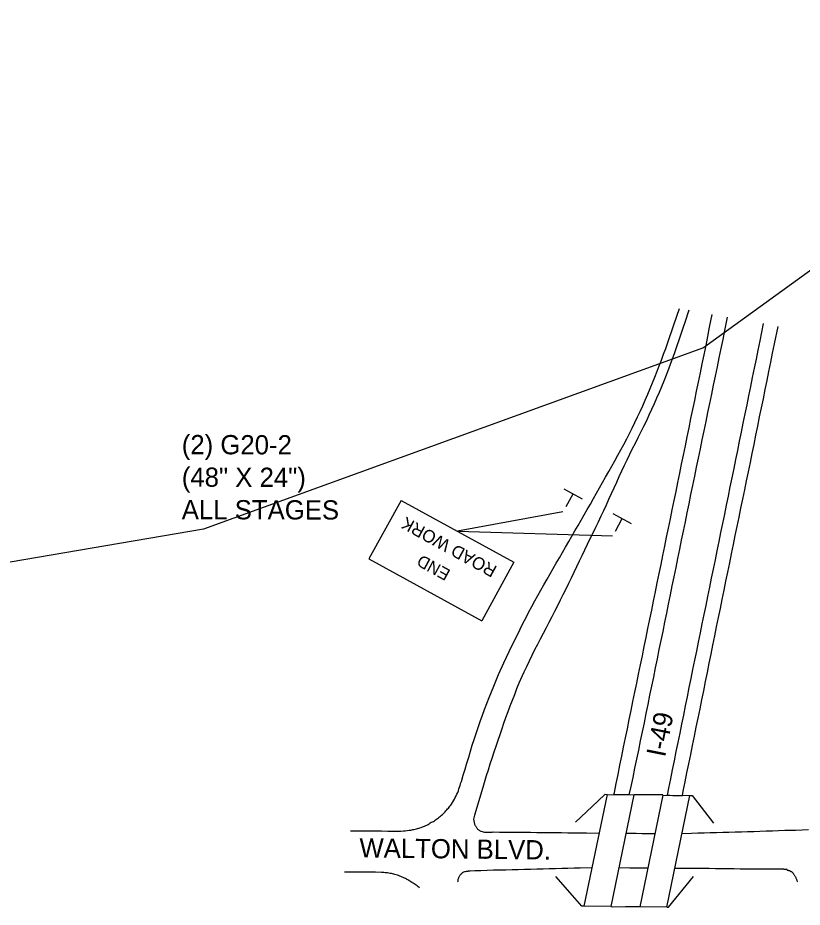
# Model space of a CAD drawing. Extents: x 1017892 to 1236694, y 658811 to 792468.
# Drawn here: x 1022369 to 1023001, y 659671 to 660387 of the extents above; entities that cross this region are included whole.
import ezdxf

# ---------------------------------------------------------------- set-up
doc = ezdxf.new("R2010")
doc.units = 0
for name, color, linetype in [('Level 3', 7, 'Continuous'), ('Level 42', 7, 'Continuous'), ('Level 8', 7, 'Continuous'), ('R_Border', 7, 'Continuous'), ('R_Proposed Road Annot', 7, 'Continuous'), ('S_BRIDGE', 7, 'Continuous'), ('S_EDGE_PAVEMENT', 7, 'Continuous'), ('S_MISC_STRUCTURES', 7, 'Continuous'), ('S_SIDEWALK', 7, 'Continuous')]:
    doc.layers.add(name, color=color, linetype=linetype)

msp = doc.modelspace()

# ---------------------------------------------------------------- linework, layer by layer
at = {"layer": 'Level 3'}
for p, q in [((1022809.12, 660007.57), (1022823.96, 659999.55)), ((1022816.38, 660003.36), (1022810.91, 659993.23)), ((1022848.64, 659987.77), (1022863.48, 659979.74)), ((1022855.91, 659983.56), (1022850.43, 659973.43))]:
    msp.add_line(p, q, dxfattribs=at)
at = {"layer": 'Level 8'}
for p, q in [((1022678.06, 659998.42), (1022652.2, 659951.32)), ((1022678.06, 659998.42), (1022768.89, 659948.54)), ((1022652.2, 659951.32), (1022743.02, 659901.44)), ((1022768.89, 659948.54), (1022743.02, 659901.44))]:
    msp.add_line(p, q, dxfattribs=at)
at = {"layer": 'R_Border'}
for points in [[(1023548.14, 660387), (1023255.62, 660362.67), (1022921.74, 660121.31)], [(1022921.74, 660121.31), (1022518.9, 659975.15), (1021256.99, 659760.06)]]:
    msp.add_lwpolyline(points, dxfattribs=at)
at = {"layer": 'R_Proposed Road Annot'}
for p, q in [((1022808.5, 659989.3), (1022723.48, 659973.48)), ((1022723.48, 659973.48), (1022848.36, 659969.93))]:
    msp.add_line(p, q, dxfattribs=at)
at = {"layer": 'S_BRIDGE'}
for points in [[(1022847.15, 659671.44), (1022825.68, 659671.68), (1022844.27, 659761.47), (1022865.63, 659761.4), (1022847.15, 659671.44)], [(1022870.74, 659671.19), (1022889.14, 659761.02), (1022910.5, 659760.84), (1022891.96, 659670.94), (1022870.74, 659671.19)]]:
    msp.add_lwpolyline(points, dxfattribs=at)
at = {"layer": 'S_EDGE_PAVEMENT'}
for points in [[(1022677.93, 659732.15), (1022679.95, 659732.26), (1022681.45, 659732.38), (1022682.95, 659732.56), (1022684.46, 659732.75), (1022685.95, 659732.94), (1022687.42, 659733.24), (1022688.43, 659733.46), (1022689.41, 659733.7), (1022690.39, 659733.94), (1022691.36, 659734.14), (1022692.33, 659734.34), (1022693.29, 659734.65), (1022694.26, 659735.04), (1022695.21, 659735.43), (1022696.18, 659735.72), (1022697.07, 659736.09), (1022698.02, 659736.51), (1022698.93, 659736.96), (1022699.83, 659737.43), (1022700.66, 659738.02), (1022701.52, 659738.62), (1022702.35, 659739.18), (1022703.28, 659739.58), (1022704.15, 659739.89), (1022705.02, 659740.37), (1022705.85, 659741.06), (1022706.69, 659741.74), (1022707.51, 659742.31), (1022708.29, 659742.88), (1022709.08, 659743.52), (1022709.86, 659744.16), (1022710.64, 659744.79), (1022711.38, 659745.47), (1022712.12, 659746.17), (1022712.83, 659746.9), (1022713.53, 659747.63), (1022714.2, 659748.37), (1022714.88, 659749.13), (1022715.54, 659749.88), (1022716.2, 659750.64), (1022716.82, 659751.43), (1022717.43, 659752.25), (1022718.04, 659753.05), (1022718.61, 659753.87), (1022719.45, 659755.13), (1022720.24, 659756.42), (1022721.01, 659757.72), (1022721.74, 659759.04), (1022722.43, 659760.39), (1022723.05, 659761.77), (1022723.67, 659763.16), (1022724.2, 659764.56), (1022724.72, 659766), (1022725.19, 659767.43), (1022725.61, 659768.88), (1022725.75, 659769.38), (1022725.9, 659769.86), (1022726.04, 659770.32), (1022726.62, 659772.15), (1022728.16, 659777.06), (1022729.65, 659782.01), (1022731.07, 659786.81), (1022732.55, 659791.73), (1022733.98, 659796.55), (1022735.42, 659801.17), (1022736.93, 659805.87), (1022738.47, 659810.67), (1022740.14, 659815.54), (1022741.77, 659820.27), (1022743.56, 659825.32), (1022745.31, 659830.06), (1022747.09, 659834.77), (1022748.96, 659839.57), (1022750.78, 659844.24), (1022752.7, 659848.85), (1022756.63, 659858.08), (1022760.84, 659867.6), (1022765.15, 659876.62), (1022767.26, 659881.15), (1022771.74, 659890.15), (1022776.23, 659899.26), (1022778.72, 659904.21), (1022781.08, 659908.61), (1022783.44, 659913.02), (1022785.8, 659917.43), (1022788.16, 659921.84), (1022790.65, 659926.18), (1022793.13, 659930.51), (1022795.62, 659934.85), (1022798.11, 659939.19), (1022800.62, 659943.52), (1022803.13, 659947.85), (1022805.64, 659952.18), (1022808.14, 659956.51), (1022810.65, 659960.84), (1022813.15, 659965.16), (1022815.65, 659969.5), (1022818.16, 659973.83), (1022820.66, 659978.16), (1022823.14, 659982.5), (1022825.63, 659986.84), (1022828.05, 659991.07), (1022830.53, 659995.41), (1022833, 659999.77), (1022835.46, 660004.12), (1022837.93, 660008.48), (1022840.38, 660012.84), (1022842.83, 660017.2), (1022845.34, 660021.66), (1022847.82, 660026), (1022850.31, 660030.34), (1022852.79, 660034.68), (1022855.13, 660039.1), (1022857.47, 660043.52), (1022859.8, 660047.94), (1022862.14, 660052.36), (1022864.23, 660056.54), (1022866.46, 660061.02), (1022868.58, 660065.55), (1022870.7, 660070.08), (1022872.76, 660074.64), (1022874.82, 660079.2), (1022876.76, 660083.8), (1022878.71, 660088.41), (1022880.61, 660093.03), (1022882.52, 660097.66), (1022884.35, 660102.32), (1022886.07, 660106.69), (1022887.78, 660111.39), (1022889.5, 660116.09), (1022891.21, 660120.78), (1022892.86, 660125.5), (1022894.52, 660130.22), (1022896.17, 660134.94), (1022897.83, 660139.66), (1022902.33, 660152.91)], [(1022909.95, 660151.53), (1022906.76, 660141.73), (1022905.15, 660137), (1022903.54, 660132.26), (1022901.94, 660127.53), (1022900.27, 660122.81), (1022898.6, 660118.1), (1022896.88, 660113.41), (1022895.15, 660108.71), (1022893.37, 660104.04), (1022891.51, 660099.15), (1022889.66, 660094.5), (1022887.81, 660089.86), (1022885.86, 660085.25), (1022883.91, 660080.65), (1022881.88, 660076.08), (1022879.85, 660071.51), (1022877.74, 660066.97), (1022875.63, 660062.44), (1022873.42, 660057.95), (1022871.21, 660053.46), (1022868.85, 660048.79), (1022866.59, 660044.32), (1022864.33, 660039.86), (1022862.07, 660035.4), (1022859.92, 660030.88), (1022857.78, 660026.36), (1022855.68, 660021.81), (1022853.58, 660017.26), (1022851.54, 660012.8), (1022849.46, 660008.25), (1022847.35, 660003.72), (1022845.24, 659999.18), (1022843.15, 659994.64), (1022841.06, 659990.09), (1022838.91, 659985.58), (1022836.7, 659980.96), (1022834.55, 659976.44), (1022832.4, 659971.92), (1022830.25, 659967.41), (1022828.09, 659962.89), (1022825.93, 659958.38), (1022823.76, 659953.87), (1022821.58, 659949.37), (1022819.41, 659944.87), (1022817.23, 659940.36), (1022815.05, 659935.86), (1022812.87, 659931.36), (1022810.69, 659926.86), (1022808.5, 659922.36), (1022806.23, 659917.92), (1022803.95, 659913.47), (1022801.67, 659909.02), (1022799.4, 659904.57), (1022797.12, 659900.12), (1022794.84, 659895.67), (1022792.43, 659891.11), (1022790.11, 659886.7), (1022787.88, 659882.37), (1022785.67, 659877.94), (1022783.43, 659873.47), (1022781.23, 659868.98), (1022779.08, 659864.47), (1022776.95, 659859.95), (1022773.06, 659851.15), (1022771.18, 659846.56), (1022769.31, 659841.92), (1022767.48, 659837.27), (1022765.65, 659832.62), (1022763.98, 659828.07), (1022762.24, 659823.41), (1022760.63, 659818.73), (1022759.11, 659814.35), (1022757.56, 659809.59), (1022755.95, 659805.02), (1022754.4, 659800.31), (1022752.72, 659795.53), (1022751.19, 659790.61), (1022749.64, 659785.87), (1022748.19, 659781.24), (1022746.71, 659776.47), (1022743.89, 659767.23), (1022739.56, 659752.89), (1022738.16, 659748.31), (1022737.26, 659744.9), (1022736.91, 659743.89), (1022736.39, 659741.64), (1022737.21, 659737.7), (1022737.41, 659737.18), (1022737.64, 659736.72), (1022737.92, 659736.3), (1022738.19, 659735.9), (1022738.49, 659735.48), (1022738.76, 659735.07), (1022739.07, 659734.64), (1022739.38, 659734.18), (1022739.72, 659733.76), (1022740.1, 659733.39), (1022740.53, 659733.05), (1022740.96, 659732.75), (1022741.37, 659732.52), (1022742.38, 659731.95), (1022743.35, 659731.65), (1022744.33, 659731.48), (1022745.32, 659731.35), (1022746.32, 659731.24)], [(1022940.85, 660145.94), (1022938.65, 660135.25), (1022937.12, 660127.91), (1022935.6, 660120.56), (1022934.07, 660113.22), (1022932.55, 660105.88), (1022931.03, 660098.54), (1022929.51, 660091.2), (1022928, 660083.86), (1022926.49, 660076.51), (1022924.97, 660069.17), (1022923.46, 660061.83), (1022921.94, 660054.49), (1022920.41, 660047.14), (1022918.89, 660039.8), (1022917.37, 660032.46), (1022915.85, 660025.12), (1022914.33, 660017.77), (1022912.82, 660010.43), (1022911.31, 660003.08), (1022909.81, 659995.74), (1022908.3, 659988.39), (1022906.79, 659981.04), (1022905.29, 659973.7), (1022903.78, 659966.35), (1022902.28, 659959.01), (1022900.77, 659951.66), (1022899.27, 659944.31), (1022897.77, 659936.96), (1022896.26, 659929.62), (1022894.77, 659922.27), (1022893.28, 659914.92), (1022891.78, 659907.57), (1022890.29, 659900.22), (1022888.8, 659892.87), (1022887.29, 659885.52), (1022885.79, 659878.18), (1022884.28, 659870.83), (1022882.78, 659863.48), (1022881.27, 659856.13), (1022879.77, 659848.79), (1022878.27, 659841.44), (1022876.77, 659834.09), (1022875.27, 659826.74), (1022873.77, 659819.39), (1022872.25, 659812.05), (1022870.73, 659804.7), (1022869.21, 659797.36), (1022867.69, 659790.01), (1022866.17, 659782.67), (1022864.63, 659775.33), (1022863.08, 659767.98), (1022861.65, 659761.19), (1022858.79, 659761.21), (1022849.53, 659761.29), (1022849.89, 659763.05), (1022851.38, 659770.4), (1022852.87, 659777.75), (1022854.36, 659785.1), (1022855.86, 659792.45), (1022857.36, 659799.8), (1022858.85, 659807.15), (1022860.35, 659814.49), (1022861.86, 659821.84), (1022863.37, 659829.19), (1022864.88, 659836.53), (1022866.39, 659843.88), (1022867.9, 659851.23), (1022869.41, 659858.57), (1022870.92, 659865.92), (1022872.43, 659873.27), (1022873.94, 659880.61), (1022875.45, 659887.96), (1022876.95, 659895.31), (1022878.44, 659902.65), (1022879.94, 659910), (1022881.43, 659917.35), (1022882.94, 659924.7), (1022884.45, 659932.05), (1022885.95, 659939.39), (1022887.46, 659946.74), (1022888.97, 659954.08), (1022890.47, 659961.43), (1022891.98, 659968.78), (1022893.5, 659976.12), (1022895.01, 659983.47), (1022896.52, 659990.81), (1022898.03, 659998.16), (1022899.54, 660005.5), (1022901.05, 660012.85), (1022902.57, 660020.19), (1022904.06, 660027.54), (1022905.56, 660034.88), (1022907.06, 660042.23), (1022908.56, 660049.58), (1022910.08, 660056.92), (1022911.6, 660064.26), (1022913.12, 660071.6), (1022914.63, 660078.95), (1022916.15, 660086.29), (1022917.67, 660093.63), (1022919.19, 660100.97), (1022920.71, 660108.31), (1022922.22, 660115.66), (1022923.74, 660123), (1022925.26, 660130.34), (1022926.45, 660137.75), (1022928.56, 660148.16)], [(1022969.8, 660140.7), (1022966.96, 660126.78), (1022965.46, 660119.43), (1022963.97, 660112.08), (1022962.47, 660104.74), (1022960.97, 660097.39), (1022959.47, 660090.05), (1022957.98, 660082.7), (1022956.48, 660075.35), (1022954.98, 660068.01), (1022953.48, 660060.66), (1022951.99, 660053.31), (1022950.49, 660045.97), (1022948.99, 660038.62), (1022947.49, 660031.27), (1022945.99, 660023.93), (1022944.5, 660016.58), (1022943, 660009.23), (1022941.5, 660001.89), (1022939.99, 659994.54), (1022938.49, 659987.19), (1022936.98, 659979.85), (1022935.48, 659972.5), (1022933.98, 659965.15), (1022932.47, 659957.81), (1022930.97, 659950.46), (1022929.47, 659943.11), (1022927.96, 659935.77), (1022926.46, 659928.42), (1022924.96, 659921.07), (1022923.45, 659913.73), (1022921.95, 659906.38), (1022920.44, 659899.02), (1022918.94, 659891.67), (1022917.44, 659884.33), (1022915.93, 659876.98), (1022914.43, 659869.63), (1022912.93, 659862.29), (1022911.42, 659854.94), (1022909.93, 659847.59), (1022908.44, 659840.24), (1022906.95, 659832.89), (1022905.46, 659825.54), (1022903.97, 659818.19), (1022902.48, 659810.84), (1022900.99, 659803.48), (1022899.5, 659796.13), (1022898.01, 659788.78), (1022896.54, 659781.43), (1022895.03, 659774.08), (1022893.55, 659766.73), (1022892.39, 659760.9), (1022894.48, 659760.89), (1022896.98, 659760.88), (1022899.48, 659760.87), (1022901.98, 659760.85), (1022903.23, 659760.85), (1022904.64, 659760.84), (1022905.35, 659764.32), (1022906.86, 659771.67), (1022908.37, 659779.02), (1022909.87, 659786.37), (1022911.37, 659793.72), (1022912.87, 659801.07), (1022914.37, 659808.41), (1022915.87, 659815.76), (1022917.36, 659823.11), (1022918.86, 659830.46), (1022920.36, 659837.81), (1022921.86, 659845.16), (1022923.36, 659852.51), (1022924.84, 659859.86), (1022926.32, 659867.21), (1022927.81, 659874.56), (1022929.29, 659881.91), (1022930.77, 659889.26), (1022932.26, 659896.61), (1022933.76, 659903.95), (1022935.27, 659911.3), (1022936.77, 659918.65), (1022938.28, 659925.99), (1022939.78, 659933.34), (1022941.28, 659940.69), (1022942.79, 659948.03), (1022944.29, 659955.38), (1022945.79, 659962.73), (1022947.29, 659970.08), (1022948.79, 659977.42), (1022950.31, 659984.77), (1022951.83, 659992.11), (1022953.35, 659999.45), (1022954.87, 660006.8), (1022956.39, 660014.14), (1022957.91, 660021.48), (1022959.42, 660028.83), (1022960.92, 660036.17), (1022962.42, 660043.52), (1022963.92, 660050.86), (1022965.42, 660058.21), (1022966.91, 660065.56), (1022968.4, 660072.91), (1022969.89, 660080.26), (1022971.38, 660087.6), (1022972.87, 660094.95), (1022974.36, 660102.3), (1022975.84, 660109.65), (1022977.33, 660116.99), (1022978.84, 660124.34), (1022981.76, 660138.53)], [(1022637.3, 659732.39), (1022642.3, 659732.37), (1022647.3, 659732.33), (1022652.3, 659732.28), (1022657.3, 659732.22), (1022662.3, 659732.16), (1022667.3, 659732.13), (1022672.3, 659732.09), (1022677.93, 659732.15)], [(1022904.19, 659730.24), (1022912.1, 659730.42), (1022917.11, 659730.56), (1022922.12, 659730.71), (1022927.12, 659730.85), (1022932.13, 659730.99), (1022937.13, 659731.13), (1022942.14, 659731.27), (1022947.15, 659731.42), (1022952.15, 659731.57), (1022957.16, 659731.72), (1022962.17, 659731.88), (1022967.17, 659732.02), (1022972.18, 659732.16), (1022977.19, 659732.33), (1022982.19, 659732.52), (1022987.2, 659732.7), (1022992.21, 659732.84), (1022995.86, 659732.95), (1023001.1, 659733.15), (1023006.28, 659733.32)], [(1022746.32, 659731.24), (1022747.35, 659731.24), (1022748.41, 659731.23), (1022749.43, 659731.25), (1022750.41, 659731.33), (1022751.41, 659731.35), (1022752.31, 659731.36), (1022757.31, 659731.31), (1022762.31, 659731.3), (1022767.31, 659731.25), (1022772.31, 659731.21), (1022777.31, 659731.15), (1022782.31, 659731.09), (1022787.31, 659731.03), (1022792.31, 659730.97), (1022797.31, 659730.92), (1022802.31, 659730.87), (1022807.31, 659730.83), (1022812.31, 659730.79), (1022817.31, 659730.75), (1022822.31, 659730.7), (1022827.31, 659730.64), (1022837.87, 659730.54)], [(1022859.24, 659730.31), (1022867.31, 659730.3), (1022872.08, 659730.27), (1022882.82, 659730.18)], [(1022662.43, 659698.79), (1022657.43, 659698.9), (1022652.43, 659698.92), (1022647.43, 659698.92), (1022642.43, 659698.94), (1022637.43, 659698.97), (1022632.44, 659698.99)], [(1022692.99, 659686.26), (1022692.61, 659686.59), (1022691.81, 659687.27), (1022691.03, 659687.9), (1022690.25, 659688.53), (1022689.43, 659689.12), (1022688.55, 659689.67), (1022687.68, 659690.21), (1022686.84, 659690.75), (1022686.01, 659691.29), (1022685.16, 659691.82), (1022684.29, 659692.33), (1022683.42, 659692.86), (1022682.56, 659693.34), (1022681.64, 659693.79), (1022680.72, 659694.24), (1022679.8, 659694.64), (1022678.87, 659695.05), (1022677.95, 659695.45), (1022677.03, 659695.84), (1022676.09, 659696.21), (1022675.13, 659696.53), (1022674.14, 659696.81), (1022673.16, 659697.1), (1022672.19, 659697.32), (1022671.19, 659697.57), (1022670.23, 659697.81), (1022669.25, 659698.02), (1022668.24, 659698.2), (1022667.24, 659698.35), (1022666.24, 659698.46), (1022665.22, 659698.55), (1022664.21, 659698.66), (1022663.22, 659698.74), (1022662.68, 659698.77), (1022662.43, 659698.79)], [(1022723.55, 659691.22), (1022723.99, 659691.84), (1022724.07, 659692.35), (1022724.1, 659692.87), (1022724.18, 659693.38), (1022724.33, 659693.88), (1022724.52, 659694.35), (1022724.7, 659694.83), (1022724.89, 659695.32), (1022725.15, 659695.77), (1022725.4, 659696.23), (1022725.69, 659696.67), (1022726.02, 659697.1), (1022726.42, 659697.48), (1022726.78, 659697.9), (1022727.19, 659698.31), (1022727.66, 659698.66), (1022728.17, 659699), (1022728.73, 659699.28), (1022729.32, 659699.53), (1022729.96, 659699.68), (1022730.64, 659699.81), (1022731.31, 659699.89), (1022732, 659699.91)], [(1022832.07, 659702.51), (1022822.43, 659702.22), (1022817.43, 659702.14), (1022812.43, 659702), (1022807.43, 659701.88), (1022802.43, 659701.76), (1022797.43, 659701.67), (1022792.43, 659701.52), (1022787.43, 659701.41), (1022782.43, 659701.29), (1022777.43, 659701.15), (1022772.43, 659701.01), (1022767.43, 659700.89), (1022762.44, 659700.74), (1022757.44, 659700.67), (1022752.44, 659700.5), (1022747.44, 659700.36), (1022742.44, 659700.17), (1022737.44, 659700.01), (1022733.74, 659699.95), (1022733.32, 659699.93), (1022732.71, 659699.87), (1022732.44, 659699.88), (1022732, 659699.91)], [(1022877.11, 659702.26), (1022867.42, 659702.33), (1022862.42, 659702.36), (1022853.51, 659702.42)], [(1022989.09, 659700.64), (1022989.1, 659701.16), (1022988.1, 659701.24), (1022987.1, 659701.26), (1022986.6, 659701.29), (1022986.27, 659701.3), (1022981.27, 659701.37), (1022976.27, 659701.43), (1022971.27, 659701.48), (1022966.27, 659701.51), (1022961.27, 659701.52), (1022956.26, 659701.51), (1022951.26, 659701.55), (1022946.26, 659701.61), (1022941.26, 659701.67), (1022936.26, 659701.72), (1022931.26, 659701.77), (1022926.26, 659701.83), (1022921.26, 659701.87), (1022916.26, 659701.9), (1022911.26, 659701.95), (1022898.39, 659702.09)], [(1022989.09, 659700.64), (1022989.43, 659700.6), (1022989.78, 659700.54), (1022990.13, 659700.46), (1022990.48, 659700.37), (1022990.82, 659700.25), (1022991.15, 659700.12), (1022991.49, 659699.98), (1022991.81, 659699.81), (1022992.12, 659699.63), (1022992.43, 659699.43), (1022992.72, 659699.22), (1022993, 659699), (1022993.27, 659698.76), (1022993.53, 659698.52), (1022993.77, 659698.26), (1022994, 659697.99)], [(1022994, 659697.99), (1022994.26, 659697.6), (1022994.53, 659697.2), (1022994.78, 659696.8), (1022995.02, 659696.39), (1022995.26, 659695.97), (1022995.49, 659695.55), (1022995.71, 659695.13), (1022995.93, 659694.7), (1022996.13, 659694.27), (1022996.33, 659693.83), (1022996.51, 659693.39), (1022996.69, 659692.95), (1022996.86, 659692.51), (1022997.02, 659692.06), (1022997.18, 659691.6), (1022997.32, 659691.15)]]:
    msp.add_lwpolyline(points, dxfattribs=at)
at = {"layer": 'S_MISC_STRUCTURES'}
for points in [[(1022818.46, 659739.19), (1022836.64, 659756.12), (1022842.47, 659761.77), (1022844.22, 659761.64)], [(1022888.92, 659761.2), (1022874.67, 659761.33), (1022865.95, 659761.34)], [(1022892.31, 659670.84), (1022893.41, 659670.79), (1022913.62, 659695.56)], [(1022870.61, 659671.18), (1022858.89, 659671.14), (1022848.68, 659670.88), (1022847.11, 659671.16)]]:
    msp.add_lwpolyline(points, dxfattribs=at)
at = {"layer": 'S_SIDEWALK'}
for points in [[(1022910.64, 659760.87), (1022912.5, 659760.85), (1022929.81, 659738.6)], [(1022825.81, 659671.71), (1022823.62, 659671.65), (1022816.08, 659680.2), (1022802.65, 659695.43)]]:
    msp.add_lwpolyline(points, dxfattribs=at)

# ---------------------------------------------------------------- texts
at = {"layer": 'Level 3'}
msp.add_text('ROAD WORK', height=10.075, rotation=151.22419, dxfattribs=at).set_placement((1022756.14, 659944.8))
at = {"layer": 'Level 42'}
msp.add_text('END', height=9.762, rotation=151.22419, dxfattribs=at).set_placement((1022718.61, 659941.83))
at = {"layer": 'Level 8'}
for s, p in [('(2) G20-2', (1022501.41, 660035.57)), ('(48" X 24")', (1022501.41, 660009.39)), ('ALL STAGES', (1022501.41, 659983.21))]:
    msp.add_text(s, height=15.5, rotation=359.87782, dxfattribs=at).set_placement(p)
at = {"layer": 'R_Proposed Road Annot'}
for s, rotation, p in [('I-49', 78.75739, (1022890.68, 659791.06)), ('WALTON BLVD.', 359.34926, (1022644.42, 659710.89))]:
    msp.add_text(s, height=15.5, rotation=rotation, dxfattribs=at).set_placement(p)

doc.saveas('drawing.dxf')
